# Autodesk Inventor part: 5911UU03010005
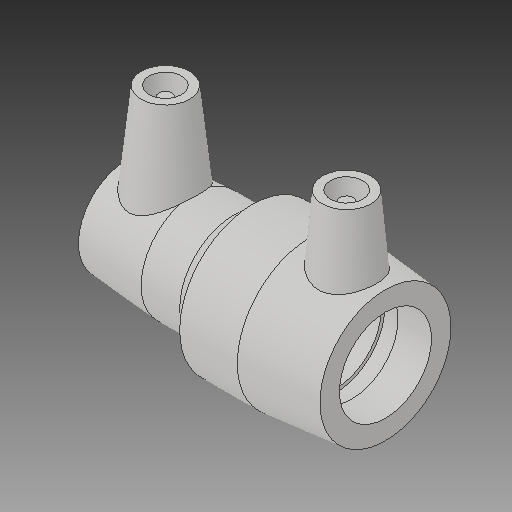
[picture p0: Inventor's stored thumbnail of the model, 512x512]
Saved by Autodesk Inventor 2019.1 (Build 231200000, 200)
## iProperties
Created: 2017-06
Part Number: 5911UU03010005
Material: Generic
Description: PLASSON ASTM REDUCING COUPLER 1''CTS-1/2''CTS
Document SubType Name: Modeling
Designer: KIM
Mass: 54.8237 g
Surface Area: 155.252 cm^2
Volume: 54.8237 cm^3
Density: 1 g/cm^3
Appearance: Default
Author: KIM
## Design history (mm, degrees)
derived "5911.ipt"
feature "Solid1::5911.ipt"
tag "TaggingFeature1"
body "Solid1"
other parameters: "d0" = 80.01, "d2" = 33.02, "d3" = 35.052, "d4" = 21.0312, "d5" = 29.718, "d7" = 15.8, "d8" = 168 deg, "d10" = 14.0208, "d11" = 4.6736, "d14" = 17.6296, "d22" = 108.92847, "d29" = 40.894, "d30" = 15, "d31" = 28.0035, "d34" = 6 deg, "d41" = 4, "d42" = 14, "d43" = 0, "d48" = 33.02, "d49" = 28.45, "d50" = 44.958, "d52" = 14.22, "d53" = 15.5448, "d54" = 5.1816, "d55" = 168 deg, "d56" = 23.3172, "d57" = 38.862, "d58" = 40.4622, "d59" = 1.7526, "d60" = 135 deg, "d61" = 40.894, "d62" = 15, "d64" = 4, "d66" = 5 deg, "d67" = 14, "d68" = 0, "d69" = 28.0035, "d95" = 3, "d96" = 0, "d97" = 3, "d98" = 0, "d_1" = 15.8, "L_" = 80.01, "L_2" = 35.052, "D_1" = 33.02, "A_1" = 40.894, "d_2" = 12, "L_1" = 38.862, "d_" = 28.45, "A_" = 40.894, "D_" = 44.958
